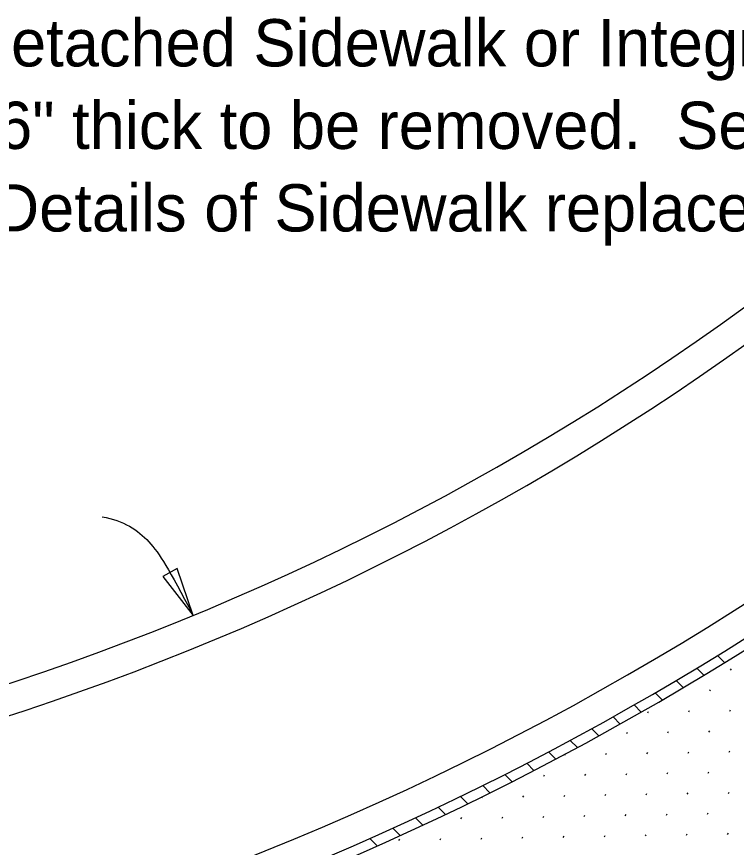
# Model space of a CAD drawing. Extents: x 21526.6 to 21595.9, y 56117 to 56157.3.
# Drawn here: x 21558.378 to 21561.449, y 56149.572 to 56153.115 of the extents above; entities that cross this region are included whole.
import ezdxf

# ---------------------------------------------------------------- set-up
doc = ezdxf.new("R2010")
doc.units = 0
for name, color, linetype in [('AdhocPoint_dp', 7, 'Continuous'), ('Patterning', 7, 'Continuous'), ('PlotBorder_dp', 7, 'Continuous')]:
    doc.layers.add(name, color=color, linetype=linetype)

msp = doc.modelspace()

# ---------------------------------------------------------------- linework, layer by layer
at = {"layer": 'AdhocPoint_dp'}
for radius, start, end in [(11.3394, 267.40102, 307.93264), (11.4702, 267.84731, 307.49092), (12.3856, 268.00648, 307.27295), (12.5106, 272.22541, 307.24718), (12.5523, 272.40859, 307.2387)]:
    msp.add_arc((21554.816, 56161.0472), radius, start, end, dxfattribs=at)
at = {"layer": 'Patterning'}
for p, q in [((21561.3686, 56150.3899), (21561.3985, 56150.36)), ((21561.2807, 56150.3364), (21561.3109, 56150.3062)), ((21561.4248, 56150.3282), (21561.4281, 56150.3338)), ((21561.1922, 56150.2834), (21561.2223, 56150.2534)), ((21561.1031, 56150.2311), (21561.1333, 56150.2009)), ((21561.3356, 56150.2389), (21561.3388, 56150.2445)), ((21561.0134, 56150.1795), (21561.0436, 56150.1492)), ((21561.071, 56150.1464), (21561.0742, 56150.152)), ((21561.2463, 56150.1496), (21561.2495, 56150.1552)), ((21561.4216, 56150.1529), (21561.4248, 56150.1585)), ((21560.923, 56150.1284), (21560.9533, 56150.0981)), ((21560.832, 56150.078), (21560.8624, 56150.0475)), ((21560.9817, 56150.0571), (21560.985, 56150.0627)), ((21561.157, 56150.0604), (21561.1603, 56150.066)), ((21561.3323, 56150.0636), (21561.3356, 56150.0692)), ((21560.7403, 56150.0282), (21560.7707, 56149.9978)), ((21560.648, 56149.9791), (21560.6787, 56149.9484)), ((21560.8925, 56149.9679), (21560.8957, 56149.9735)), ((21561.0678, 56149.9711), (21561.071, 56149.9767)), ((21561.2431, 56149.9743), (21561.2463, 56149.9799)), ((21561.4184, 56149.9776), (21561.4216, 56149.9832)), ((21560.7171, 56149.9646), (21560.7204, 56149.9702)), ((21560.5551, 56149.9306), (21560.5856, 56149.9001)), ((21560.4615, 56149.8828), (21560.4925, 56149.8518)), ((21560.6279, 56149.8753), (21560.6311, 56149.8809)), ((21560.8032, 56149.8786), (21560.8064, 56149.8842)), ((21560.9785, 56149.8818), (21560.9817, 56149.8874)), ((21561.1538, 56149.8851), (21561.157, 56149.8907)), ((21561.3291, 56149.8883), (21561.3323, 56149.8939)), ((21560.3672, 56149.8357), (21560.3979, 56149.8049)), ((21560.7139, 56149.7893), (21560.7171, 56149.7949)), ((21560.8892, 56149.7926), (21560.8925, 56149.7982)), ((21561.0645, 56149.7958), (21561.0678, 56149.8014)), ((21561.2398, 56149.799), (21561.2431, 56149.8046)), ((21561.4151, 56149.8023), (21561.4184, 56149.8079)), ((21560.2723, 56149.7892), (21560.3034, 56149.7581)), ((21560.3633, 56149.7828), (21560.3665, 56149.7884)), ((21560.5386, 56149.7861), (21560.5418, 56149.7917)), ((21560.1767, 56149.7433), (21560.2076, 56149.7124)), ((21560.0804, 56149.6982), (21560.1116, 56149.667)), ((21560.274, 56149.6936), (21560.2773, 56149.6992)), ((21560.4493, 56149.6968), (21560.4526, 56149.7024)), ((21560.6246, 56149.7), (21560.6279, 56149.7056)), ((21560.7999, 56149.7033), (21560.8032, 56149.7089)), ((21560.9752, 56149.7065), (21560.9785, 56149.7121)), ((21561.1505, 56149.7098), (21561.1538, 56149.7154)), ((21561.3258, 56149.713), (21561.3291, 56149.7186)), ((21559.9835, 56149.6537), (21560.0146, 56149.6226)), ((21560.7107, 56149.614), (21560.7139, 56149.6196)), ((21560.886, 56149.6173), (21560.8892, 56149.6229)), ((21561.0613, 56149.6205), (21561.0645, 56149.6261)), ((21561.2366, 56149.6237), (21561.2398, 56149.6293)), ((21561.4119, 56149.627), (21561.4151, 56149.6326)), ((21559.8858, 56149.6099), (21559.9171, 56149.5786)), ((21560.0095, 56149.6011), (21560.0127, 56149.6066)), ((21560.1848, 56149.6043), (21560.188, 56149.6099)), ((21560.3601, 56149.6075), (21560.3633, 56149.6131)), ((21560.5354, 56149.6108), (21560.5386, 56149.6164))]:
    msp.add_line(p, q, dxfattribs=at)
at = {"layer": 'PlotBorder_dp'}
msp.add_lwpolyline([(21559.1317, 56150.5612), (21559.0636, 56150.7612), (21559.0015, 56150.7276)], close=True, dxfattribs=at)
msp.add_open_spline([(21558.7428, 56150.9817), (21558.8351, 56150.9658), (21558.9544, 56150.8862), (21559.0261, 56150.7613), (21559.1317, 56150.5612)], degree=3, dxfattribs=at)

# ---------------------------------------------------------------- texts
for s, p in [('Existing Detached Sidewalk or Integral Sidewalk ', (21557.1409, 56152.9026)), ('less than 6" thick to be removed.  See Roadway ', (21557.1409, 56152.5506)), ('Plans for Details of Sidewalk replacement.', (21557.1409, 56152.1986))]:
    msp.add_text(s, height=0.2016, dxfattribs=at).set_placement(p)

doc.saveas('drawing.dxf')
